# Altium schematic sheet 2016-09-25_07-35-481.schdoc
size 417 x 195 mm; SheetNumber: 1; SheetTotal: 1
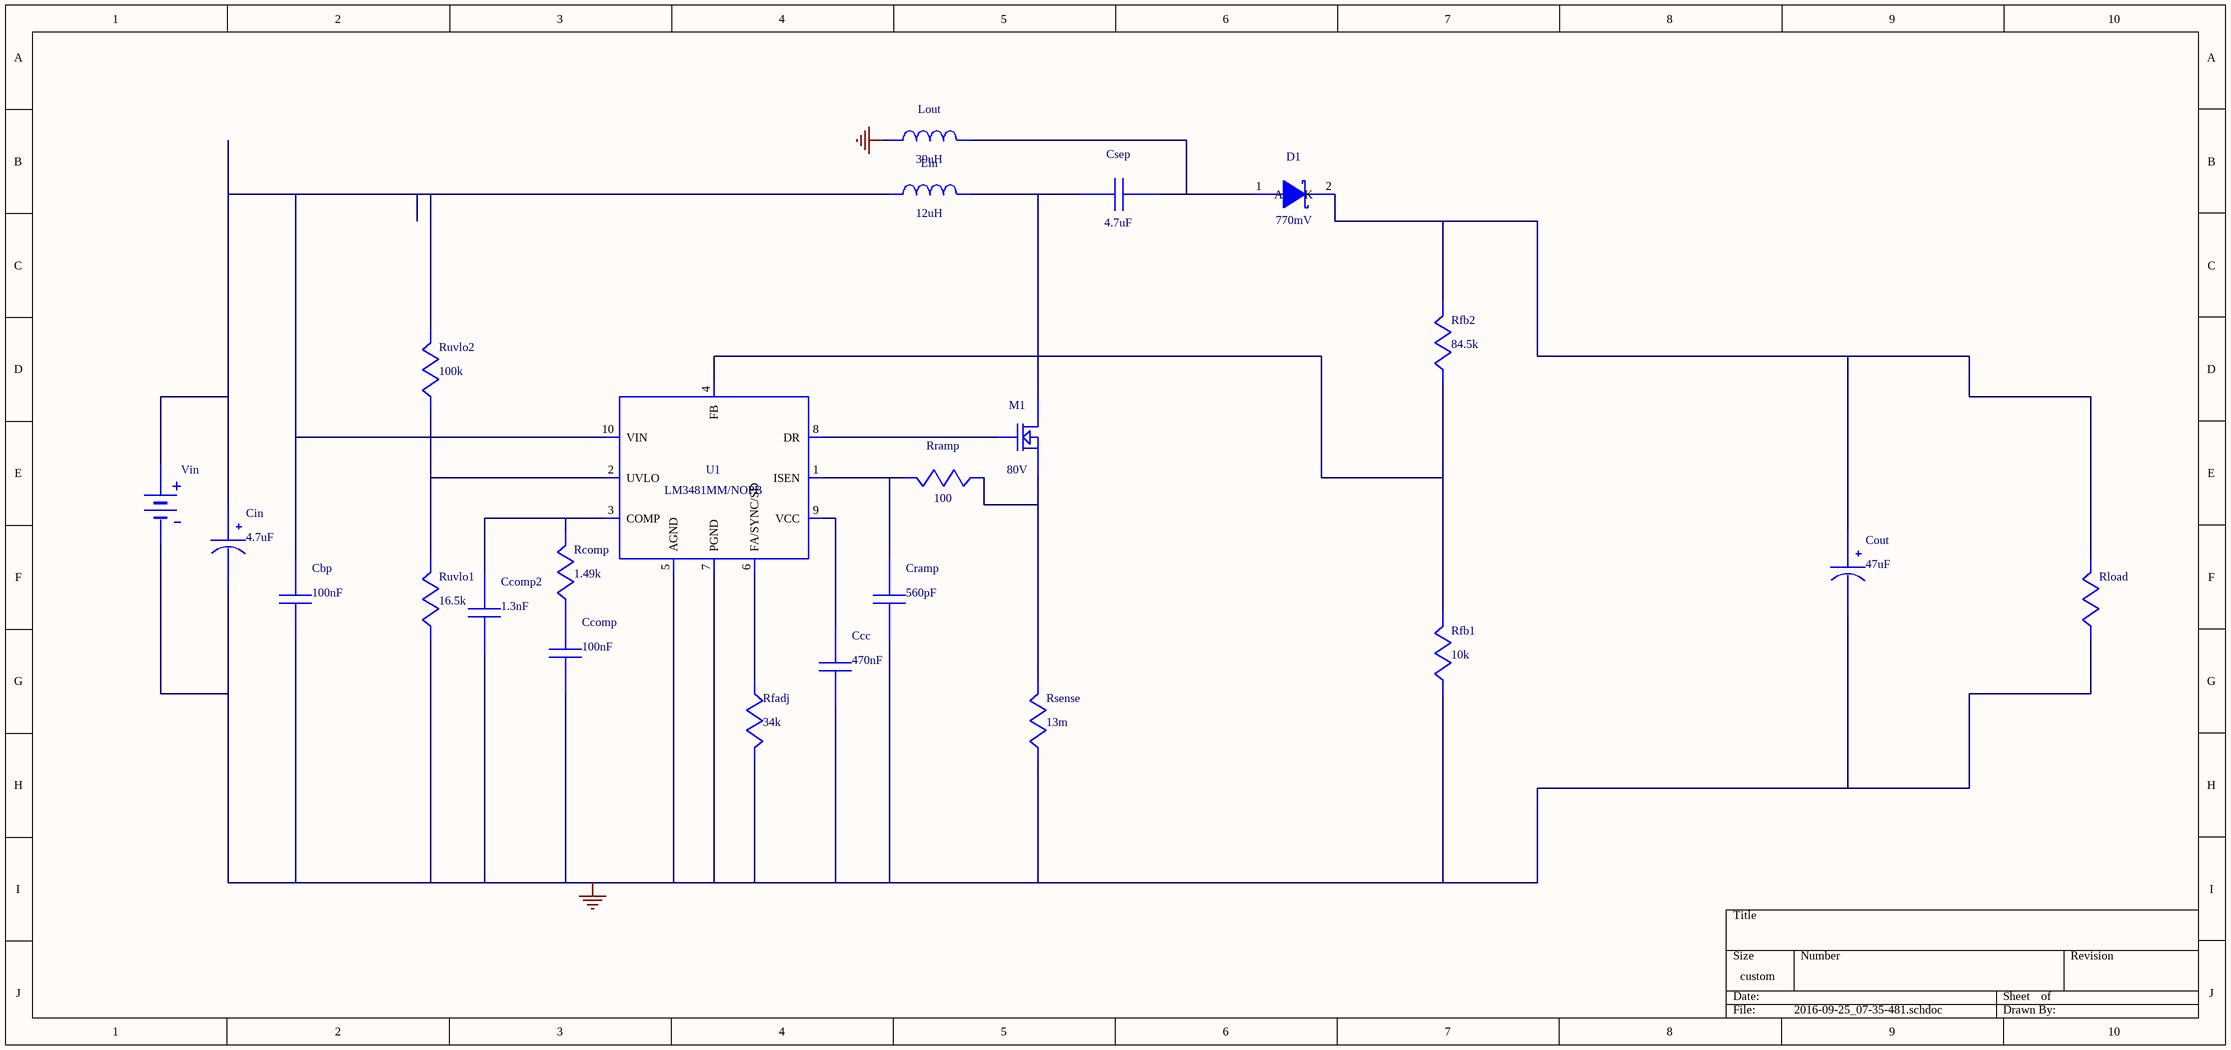
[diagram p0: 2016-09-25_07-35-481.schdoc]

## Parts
Cbp  value 100nF  (hidden comment: C0603C104K5RACTU)
Ccc  value 470nF  (hidden comment: GRM155R61A474KE15D)
Ccomp  value 100nF  (hidden comment: GRM21BR71E104KA01L)
Ccomp2  value 1.3nF  (hidden comment: GRM2165C2A132JA01D)
Cin  value 4.7uF  (hidden comment: 593D475X9050D2TE3)
Cout  value 47uF  (hidden comment: 16SVPG47M)
Cramp  value 560pF  (hidden comment: CL21C561JBANFNC)
Csep  value 4.7uF  (hidden comment: GRM31CR71H475KA12L)
D1  value 770mV  (hidden comment: 50WQ10FNPBF)
Lin  value 12uH  (hidden comment: SDR1307-120ML)
Lout  value 39uH  (hidden comment: SDR1307-390KL)
M1  value 80V  (hidden comment: BSC340N08NS3 G)
Rcomp  value 1.49k  (hidden comment: RT0805BRD071K49L)
Rfadj  value 34k  (hidden comment: CRCW040234K0FKED)
Rfb1  value 10k  (hidden comment: CRCW040210K0FKED)
Rfb2  value 84.5k  (hidden comment: CRCW040284K5FKED)
Rload  WB_LOAD_RESISTOR  (value not drawn)
Rramp  value 100  (hidden comment: CRCW0402100RFKED)
Rsense  value 13m  (hidden comment: PRL1632-R013-F-T1)
Ruvlo1  value 16.5k  (hidden comment: CRCW040216K5FKED)
Ruvlo2  value 100k  (hidden comment: CRCW0402100KFKED)
U1  LM3481MM/NOPB
Vin  WB_BATTERY  (value not drawn)

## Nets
0: Cbp.2 Ccc.2 Ccomp.2 Ccomp2.2 Cin.2(-) Cout.2(-) Cramp.2 Lout.1 Rfadj.1 Rfb1.2 Rload.2 Rsense.2 Ruvlo1.2 U1.5(AGND) U1.7(PGND) Vin.2(-)
NetCbp_1: Cbp.1 Cin.1(+) Lin.1 Ruvlo2.1 U1.10(VIN) Vin.1(+)
NetCcc_1: Ccc.1 U1.9(VCC)
NetCcomp2_1: Ccomp2.1 Rcomp.1 U1.3(COMP)
NetCcomp_1: Ccomp.1 Rcomp.2
NetCout_1: Cout.1(+) D1.2(K) Rfb2.1 Rload.1
NetCramp_1: Cramp.1 Rramp.1 U1.1(ISEN)
NetCsep_1: Csep.1 D1.1(A) D1.3(A) Lout.2
NetCsep_2: Csep.2 Lin.2 M1.5(Drain) M1.6(Drain) M1.7(Drain) M1.8(Drain) M1.9(Drain)
NetM1_1: M1.1(Source) M1.2(Source) M1.3(Source) Rramp.2 Rsense.1
NetM1_4: M1.4(Gate) U1.8(DR)
NetRfadj_2: Rfadj.2 U1.6(FA/SYNC/SD)
NetRfb1_1: Rfb1.1 Rfb2.2 U1.4(FB)
NetRuvlo1_1: Ruvlo1.1 Ruvlo2.2 U1.2(UVLO)

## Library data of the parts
Cbp = C0603C104K5RACTU: Manufacturer Name: Kemet
Ccc = GRM155R61A474KE15D: GRM155R61A474KE1; Manufacturer Name: MuRata
Ccomp = GRM21BR71E104KA01L: GRM21BR71E104KA0; Manufacturer Name: MuRata
Ccomp2 = GRM2165C2A132JA01D: GRM2165C2A132JA0; Manufacturer Name: MuRata
Cin = 593D475X9050D2TE3: 593D475X9050D2TE; Manufacturer Name: Vishay-Sprague
Cout = 16SVPG47M: Manufacturer Name: Panasonic
Cramp = CL21C561JBANFNC: Manufacturer Name: Samsung Electro-Mechanics
Csep = GRM31CR71H475KA12L: GRM31CR71H475KA1; Manufacturer Name: MuRata
D1 = 50WQ10FNPBF: Manufacturer Name: Vishay-Semiconductor
Lin = SDR1307-120ML: Manufacturer Name: Bourns
Lout = SDR1307-390KL: Manufacturer Name: Bourns
M1 = BSC340N08NS3 G: Manufacturer Name: Infineon Technologies
Rcomp = RT0805BRD071K49L: Manufacturer Name: Yageo America
Rfadj = CRCW040234K0FKED: Manufacturer Name: Vishay-Dale
Rfb1 = CRCW040210K0FKED: Manufacturer Name: Vishay-Dale
Rfb2 = CRCW040284K5FKED: Manufacturer Name: Vishay-Dale
Rramp = CRCW0402100RFKED: Manufacturer Name: Vishay-Dale
Rsense = PRL1632-R013-F-T1: PRL1632-R013-F-T; Manufacturer Name: Susumu Co Ltd
Ruvlo1 = CRCW040216K5FKED: Manufacturer Name: Vishay-Dale
Ruvlo2 = CRCW0402100KFKED: Manufacturer Name: Vishay-Dale
U1 = LM3481MM/NOPB: Manufacturer Name: Texas Instruments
